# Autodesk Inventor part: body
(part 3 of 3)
sketch "Sketch150"
  geometry: L1 (-115, 140.221)-(-115, 134.332) reference; L2 (-115, 134.332)-(-122.377, 134.332) reference; L3 (-122.377, 134.332)-(-122.377, 140.221) reference; L4 (-122.377, 140.221)-(-115, 140.221) reference; L5 (-131, 141.166)-(-131, 148) reference; L6 (-131, 148)-(-123.589, 148) reference; L7 (-123.589, 148)-(-123.589, 141.166) reference; L8 (-123.589, 141.166)-(-131, 141.166) reference; L9 (-115, 141.166)-(-122.377, 141.166) reference; L10 (-122.377, 141.166)-(-122.377, 148) reference; L11 (-122.377, 148)-(-115, 148) reference; L12 (-115, 148)-(-115, 141.166) reference; L13 (-131, 140.221)-(-123.589, 140.221) reference; L14 (-123.589, 140.221)-(-123.589, 134.332) reference; L15 (-123.589, 134.332)-(-131, 134.332) reference; L16 (-131, 134.332)-(-131, 140.221) reference; L17 (-113.739, 149.568)-(-132.264, 149.568); L18 (-132.264, 149.568)-(-132.264, 132.978); L19 (-132.264, 132.978)-(-113.739, 132.978); L20 (-113.739, 132.978)-(-113.739, 149.568); 1 further point
  constraints: 8 end point, 2 parallel, 1 horizontal, 1 perpendicular
extrude "Extrusion150" cut sketch "Sketch150" distance "d349" = 1.25; taper "d350" = 0 deg
sketch "Sketch151"
  geometry: L1 (126.488, 149.508)-(126.488, 118) reference; L2 (126.488, 118)-(100, 118) reference; L3 (100, 118)-(100, 149.508) reference; L4 (100, 149.508)-(126.488, 149.508) reference; L5 (125.254, 134.332)-(101.544, 134.332); L6 (101.544, 134.332)-(101.544, 148.025); L7 (101.544, 148.025)-(125.254, 148.025); L8 (125.254, 148.025)-(125.254, 134.332); L9 (125.254, 132.001)-(101.544, 132.001); L10 (101.544, 132.001)-(101.544, 118.95); L11 (101.544, 118.95)-(125.254, 118.95); L12 (125.254, 118.95)-(125.254, 132.001); 1 further point
  constraints: 16 end point, 4 parallel, 2 horizontal, 2 perpendicular
extrude "Extrusion151" join sketch "Sketch151" distance "d351" = 1.25; taper "d352" = 0 deg
sketch "Sketch152"
  geometry: L1 (-125.254, 134.332)-(-125.254, 148.025) reference; L2 (-125.254, 148.025)-(-101.544, 148.025) reference; L3 (-101.544, 148.025)-(-101.544, 134.332) reference; L4 (-101.544, 134.332)-(-125.254, 134.332) reference; L5 (-126.488, 118)-(-126.488, 149.508) reference; L6 (-100, 149.508)-(-100, 118) reference; L7 (-126.488, 149.508)-(-100, 149.508) reference; L8 (-126.488, 132.993)-(-100, 132.993); 1 further point
  constraints: 2 end point, 2 point on line, 1 parallel
extrude "Extrusion152" join sketch "Sketch152" distance "d353" = 1.25; taper "d354" = 0 deg
sketch "Sketch153"
  geometry: L1 (101.544, 118.95)-(101.544, 132.001) reference; L2 (125.254, 132.001)-(125.254, 118.95) reference; L3 (125.254, 118.95)-(101.544, 118.95) reference; L4 (125.254, 148.025)-(125.254, 134.332) reference; L5 (101.544, 134.332)-(101.544, 148.025) reference; L6 (101.544, 148.025)-(125.254, 148.025) reference; L7 (125.254, 141.178)-(101.544, 141.178); L8 (101.544, 141.178)-(101.544, 140.119); L9 (101.544, 140.119)-(125.254, 140.119); L10 (125.254, 140.119)-(125.254, 141.178); L11 (125.254, 126.04)-(101.544, 126.04); L12 (101.544, 126.04)-(101.544, 124.925); L13 (101.544, 124.925)-(125.254, 124.925); L14 (125.254, 124.925)-(125.254, 126.04); L15 (108.73, 148.025)-(109.845, 148.025); L16 (109.845, 148.025)-(109.845, 118.95); L17 (109.845, 118.95)-(108.73, 118.95); L18 (108.73, 118.95)-(108.73, 148.025); L19 (117.478, 148.025)-(118.766, 148.025); L20 (118.766, 148.025)-(118.766, 118.95); L21 (118.766, 118.95)-(117.478, 118.95); L22 (117.478, 118.95)-(117.478, 148.025); 1 further point
  constraints: 32 end point, 8 parallel, 7 point on line, 4 horizontal, 4 perpendicular, 1 midpoint
extrude "Extrusion153" join sketch "Sketch153" distance "d355" = 0.75; taper "d356" = 0 deg
sketch "Sketch154"
  geometry: L1 (-117.478, 134.332)-(-118.766, 134.332) reference; L2 (-117.478, 134.332)-(-117.478, 140.119) reference; L3 (-117.478, 140.119)-(-109.845, 140.119) reference; L4 (-109.845, 140.119)-(-109.845, 134.332) reference; L5 (-108.73, 134.332)-(-109.845, 134.332) reference; L6 (-108.73, 134.332)-(-108.73, 140.119) reference; L7 (-108.73, 140.119)-(-101.544, 140.119) reference; L8 (-101.544, 141.178)-(-101.544, 140.119) reference; L9 (-101.544, 141.178)-(-108.73, 141.178) reference; L10 (-108.73, 141.178)-(-108.73, 148.025) reference; L11 (-109.845, 148.025)-(-108.73, 148.025) reference; L12 (-109.845, 148.025)-(-109.845, 141.178) reference; L13 (-109.845, 141.178)-(-117.478, 141.178) reference; L14 (-117.478, 141.178)-(-117.478, 148.025) reference; L15 (-118.766, 148.025)-(-117.478, 148.025) reference; L16 (-118.766, 148.025)-(-118.766, 141.178) reference; L17 (-118.766, 141.178)-(-125.254, 141.178) reference; L18 (-125.254, 140.119)-(-125.254, 141.178) reference; L19 (-125.254, 140.119)-(-118.766, 140.119) reference; L20 (-118.766, 140.119)-(-118.766, 134.332) reference; 1 further point
extrude "Extrusion154" join sketch "Sketch154" distance "d357" = 0.75; taper "d358" = 0 deg
sketch "Sketch155"
  geometry: L1 (117.478, 134.332)-(109.845, 134.332) reference; L2 (109.845, 134.332)-(109.845, 140.119) reference; L3 (109.845, 140.119)-(117.478, 140.119) reference; L4 (117.478, 140.119)-(117.478, 134.332) reference; L5 (108.73, 134.332)-(101.544, 134.332) reference; L6 (101.544, 134.332)-(101.544, 140.119) reference; L7 (101.544, 140.119)-(108.73, 140.119) reference; L8 (108.73, 140.119)-(108.73, 134.332) reference; L9 (118.766, 134.332)-(118.766, 140.119) reference; L10 (118.766, 140.119)-(125.254, 140.119) reference; L11 (125.254, 140.119)-(125.254, 134.332) reference; L12 (125.254, 134.332)-(118.766, 134.332) reference; L13 (101.544, 141.178)-(101.544, 148.025) reference; L14 (101.544, 148.025)-(108.73, 148.025) reference; L15 (108.73, 148.025)-(108.73, 141.178) reference; L16 (108.73, 141.178)-(101.544, 141.178) reference; L17 (109.845, 148.025)-(117.478, 148.025) reference; L18 (117.478, 148.025)-(117.478, 141.178) reference; L19 (117.478, 141.178)-(109.845, 141.178) reference; L20 (109.845, 141.178)-(109.845, 148.025) reference; L21 (125.254, 141.178)-(118.766, 141.178) reference; L22 (118.766, 141.178)-(118.766, 148.025) reference; L23 (118.766, 148.025)-(125.254, 148.025) reference; L24 (125.254, 148.025)-(125.254, 141.178) reference; L25 (99.825, 132.904)-(126.573, 132.904); L26 (126.573, 132.904)-(126.573, 149.564); L27 (126.573, 149.564)-(99.825, 149.564); L28 (99.825, 149.564)-(99.825, 132.904); 1 further point
  constraints: 8 end point, 2 parallel, 1 horizontal, 1 perpendicular
extrude "Extrusion155" cut sketch "Sketch155" distance "d359" = 0.75; taper "d360" = 0 deg
sketch "Sketch156"
  geometry: L1 (-132.114, -65.343)-(-128.305, -65.343); L2 (-128.305, -65.343)-(-128.305, -73.595); L3 (-128.305, -73.595)-(-132.114, -73.595); L4 (-132.114, -73.595)-(-132.114, -65.343); 1 further point
  constraints: 8 end point, 2 parallel, 1 horizontal, 1 perpendicular
extrude "Extrusion156" join sketch "Sketch156" distance "d361" = 6; taper "d363" = 0 deg; dims "d362" = 135.125, "d364" = 0
chamfer "Chamfer10" distance "d365" = 2; stored, may be unused: second distance "d366" = 2, angle "d367" = 45 deg
chamfer "Chamfer11" distance "d368" = 2.99; stored, may be unused: second distance "d369" = 2, angle "d370" = 45 deg
chamfer "Chamfer12" distance "d371" = 6.6; stored, may be unused: second distance "d372" = 2, angle "d373" = 45 deg
chamfer "Chamfer13" distance "d374" = 6.49; stored, may be unused: second distance "d375" = 2, angle "d376" = 45 deg
chamfer "Chamfer14" distance "d377" = 6.49; stored, may be unused: second distance "d378" = 2, angle "d379" = 45 deg
sketch "Sketch157"
  geometry: L1 (86, -22.522)-(104, -22.522) reference; L2 (104, -55)-(86, -55) reference; L3 (26, -55)-(8, -55) reference; L4 (8, -22.522)-(26, -22.522) reference; L5 (26, -22.522)-(26, -55) reference; L6 (17, -22.522)-(16, -22.522); L7 (16, -22.522)-(16, -55); L8 (16, -55)-(17, -55); L9 (17, -55)-(17, -22.522); L10 (17, -55)-(18, -55); L11 (18, -55)-(18, -22.522); L12 (18, -22.522)-(17, -22.522); L13 (17, -22.522)-(17, -55); L14 (95, -22.522)-(94, -22.522); L15 (94, -22.522)-(94, -55); L16 (94, -55)-(95, -55); L17 (95, -55)-(95, -22.522); L18 (95, -55)-(96, -55); L19 (96, -55)-(96, -22.522); L20 (96, -22.522)-(95, -22.522); L21 (95, -22.522)-(95, -55); L22 (104.519, -39.261)-(85.481, -39.261); L23 (85.481, -39.261)-(85.481, -38.261); L24 (85.481, -38.261)-(104.519, -38.261); L25 (104.519, -38.261)-(104.519, -39.261); L26 (104.519, -39.261)-(85.481, -38.261); L27 (85.481, -39.261)-(104.519, -38.261); L28 (8, -39.761)-(26, -39.761); L29 (26, -39.761)-(26, -38.761); L30 (26, -38.761)-(8, -38.761); L31 (8, -38.761)-(8, -39.761); L32 (8, -39.761)-(26, -38.761); L33 (26, -39.761)-(8, -38.761); 3 further points
  constraints: 56 end point, 12 parallel, 8 midpoint, 6 horizontal, 6 perpendicular, 5 point on line
  dimensions: "d380" = 1 distance of L8.end L7.end; "d381" = 1 distance of L12.end L11.end; "d382" = 1 distance of L16.end L15.end; "d383" = 1 distance of L20.end L19.end; "d384" = 1 distance of L22.end L23.end
extrude "Extrusion157" join sketch "Sketch157" distance "d385" = 2; taper "d386" = 0 deg
sketch "Sketch158"
  geometry: L1 (104.795, -31.141)-(85.205, -31.141); L2 (85.205, -31.141)-(85.205, -30.141); L3 (85.205, -30.141)-(104.795, -30.141); L4 (104.795, -30.141)-(104.795, -31.141); L5 (104.795, -31.141)-(85.205, -30.141); L6 (85.205, -31.141)-(104.795, -30.141); L7 (105.662, -47.88)-(84.338, -47.88); L8 (84.338, -47.88)-(84.338, -46.88); L9 (84.338, -46.88)-(105.662, -46.88); L10 (105.662, -46.88)-(105.662, -47.88); L11 (105.662, -47.88)-(84.338, -46.88); L12 (84.338, -47.88)-(105.662, -46.88); L13 (6.154, -30.141)-(27.846, -30.141); L14 (27.846, -30.141)-(27.846, -31.141); L15 (27.846, -31.141)-(6.154, -31.141); L16 (6.154, -31.141)-(6.154, -30.141); L17 (6.154, -30.141)-(27.846, -31.141); L18 (27.846, -30.141)-(6.154, -31.141); L19 (6.926, -46.88)-(27.074, -46.88); L20 (27.074, -46.88)-(27.074, -47.88); L21 (27.074, -47.88)-(6.926, -47.88); L22 (6.926, -47.88)-(6.926, -46.88); L23 (6.926, -46.88)-(27.074, -47.88); L24 (27.074, -46.88)-(6.926, -47.88); 5 further points
  constraints: 48 end point, 8 midpoint, 8 parallel, 4 horizontal, 4 perpendicular
  dimensions: "d387" = 1 distance of L1.end L2.end; "d388" = 1 distance of L7.end L8.end
extrude "Extrusion158" join sketch "Sketch158" distance "d389" = 2; taper "d390" = 0 deg
sketch "Sketch159"
  geometry: L1 (14, -178)-(126, -178) reference; L2 (31.976, -34.46)-(20.875, -34.46) reference; L3 (120.832, -178)-(115.933, -182.888); L4 (115.933, -182.888)-(24.079, -182.888); L5 (24.079, -182.888)-(19.202, -178); 1 further point
  constraints: 6 end point, 2 point on line, 1 parallel, 1 perpendicular
extrude "Extrusion159" join sketch "Sketch159" distance "d391" = 4.00022; taper "d392" = 0 deg
sketch "Sketch160"
  geometry: L1 (78, -15)-(34, -15); L2 (34, -15)-(34, -124); L3 (34, -124)-(78, -124); L4 (78, -124)-(78, -15); 1 further point
  constraints: 8 end point, 2 parallel, 1 horizontal, 1 perpendicular
extrude "Extrusion160" join sketch "Sketch160" distance "d393" = 4; taper "d394" = 0 deg
fillet "Fillet4" dims "d395" = 10
chamfer "Chamfer15" distance "d396" = 4; stored, may be unused: second distance "d397" = 2, angle "d398" = 45 deg
sketch "Sketch161"
  geometry: L1 (74, -47.663)-(74, -114) reference; L2 (56, -56)-(56, -32); L3 (53, -56)-(53, -32); L4 (59, -32)-(59, -56); L5 (56, -107)-(56, -83); L6 (53, -107)-(53, -83); L7 (59, -83)-(59, -107); C1 r 7 at (56, -107); C2 r 7 at (56, -56); A1 r 3 centre (56, -56) between (53, -56) and (59, -56); A2 r 3 centre (56, -32) between (59, -32) and (53, -32); A3 r 3 centre (56, -107) between (53, -107) and (59, -107); A4 r 3 centre (56, -83) between (59, -83) and (53, -83); 3 further points
  constraints: 16 end point, 8 point on circle, 8 tangent, 6 centre point, 4 parallel, 2 midpoint
extrude "Extrusion161" cut sketch "Sketch161" distance "d399" = 10.75; taper "d400" = 0 deg
sketch "Sketch162"
  geometry: L1 (53, -49.675)-(53, -32) reference; L2 (59, -32)-(59, -49.675) reference; L3 (53, -100.675)-(53, -83) reference; L4 (59, -83)-(59, -100.675) reference; L5 (38, -114)-(38, -47.663) reference; L6 (56, -107)-(56, -83); L7 (49, -107)-(49, -83); L8 (63, -83)-(63, -107); L9 (56, -56)-(56, -32); L10 (49, -56)-(49, -32); L11 (63, -32)-(63, -56); A1 r 3 centre (56, -32) between (59, -32) and (53, -32) reference; A2 r 7 centre (56, -56) between (53, -49.675) and (59, -49.675) reference; A3 r 3 centre (56, -83) between (59, -83) and (53, -83) reference; A4 r 7 centre (56, -107) between (53, -100.675) and (59, -100.675) reference; A5 r 7 centre (56, -107) between (49, -107) and (63, -107); A6 r 7 centre (56, -83) between (63, -83) and (49, -83); A7 r 7 centre (56, -56) between (49, -56) and (63, -56); A8 r 7 centre (56, -32) between (63, -32) and (49, -32); 3 further points
  constraints: 16 end point, 8 point on circle, 8 tangent, 4 centre point, 4 parallel, 2 midpoint
extrude "Extrusion162" cut sketch "Sketch162" distance "d401" = 4; taper "d402" = 0 deg
chamfer "Chamfer16" distance "d403" = 3; stored, may be unused: second distance "d404" = 2, angle "d405" = 45 deg
fillet "Fillet5" dims "d406" = 6
sketch "Sketch163"
  geometry: L1 (0, 0)-(0, 86) reference; L2 (112, 0)-(0, 0); L3 (0, 0)-(0, 5); L4 (0, 5)-(112, 5); L5 (112, 5)-(112, 0); 1 further point
  constraints: 8 end point, 2 parallel, 1 horizontal, 1 perpendicular, 1 point on line
extrude "Extrusion163" join sketch "Sketch163" distance "d407" = 6; taper "d408" = 0 deg
chamfer "Chamfer17" distance "d409" = 6; stored, may be unused: second distance "d410" = 2, angle "d411" = 45 deg
sketch "Sketch164"
  geometry: L1 (112, -66.522)-(107, -66.522); L2 (107, -66.522)-(107, -62); L3 (107, -62)-(112, -62); L4 (112, -62)-(112, -66.522); L5 (0, -66.522)-(5, -66.522); L6 (5, -66.522)-(5, -62); L7 (5, -62)-(0, -62); L8 (0, -62)-(0, -66.522); 1 further point
  constraints: 16 end point, 4 parallel, 2 horizontal, 2 perpendicular
extrude "Extrusion164" join sketch "Sketch164" distance "d412" = 87; taper "d413" = 0 deg
chamfer "Chamfer18" distance "d414" = 5; stored, may be unused: second distance "d415" = 2, angle "d416" = 45 deg
sketch "Sketch165"
  geometry: L1 (14, -200)-(14, -178) reference; L2 (115.933, -182.888)-(120.832, -178) reference; L3 (126, -178)-(126, -200) reference; L4 (31.976, -34.46)-(20.875, -34.46) reference; L5 (14, -196.844)-(18.833, -196.844); L6 (18.833, -196.844)-(18.833, -186.125); L7 (18.833, -186.125)-(14, -181.281); L8 (126, -196.844)-(121.146, -196.844); L9 (121.146, -196.844)-(121.146, -186.125); L10 (121.146, -186.125)-(126, -181.282); 1 further point
  constraints: 12 end point, 5 perpendicular, 4 point on line, 1 parallel
extrude "Extrusion165" join sketch "Sketch165" distance "d417" = 90.22222; taper "d418" = 0 deg
chamfer "Chamfer19" distance "d419" = 4.75; stored, may be unused: second distance "d420" = 2, angle "d421" = 45 deg
chamfer "Chamfer20" distance "d422" = 1; stored, may be unused: second distance "d423" = 2, angle "d424" = 45 deg
chamfer "Chamfer21" distance "d425" = 0.5; stored, may be unused: second distance "d426" = 2, angle "d427" = 45 deg
chamfer "Chamfer22" distance "d428" = 0.5; stored, may be unused: second distance "d429" = 2, angle "d430" = 45 deg
chamfer "Chamfer23" distance "d431" = 0.5; stored, may be unused: second distance "d432" = 2, angle "d433" = 45 deg
chamfer "Chamfer24" distance "d434" = 0.5; stored, may be unused: second distance "d435" = 2, angle "d436" = 45 deg
chamfer "Chamfer25" distance "d437" = 0.5; stored, may be unused: second distance "d438" = 2, angle "d439" = 45 deg
chamfer "Chamfer26" distance "d440" = 0.5; stored, may be unused: second distance "d441" = 2, angle "d442" = 45 deg
chamfer "Chamfer27" distance "d443" = 2; stored, may be unused: second distance "d444" = 0.5, angle "d445" = 45 deg
chamfer "Chamfer28" distance "d446" = 2; stored, may be unused: second distance "d447" = 0.5, angle "d448" = 45 deg
chamfer "Chamfer29" distance "d449" = 2; stored, may be unused: second distance "d450" = 0.5, angle "d451" = 45 deg
chamfer "Chamfer30" distance "d452" = 2; stored, may be unused: second distance "d453" = 0.5, angle "d454" = 45 deg
chamfer "Chamfer31" distance "d455" = 1.5; stored, may be unused: second distance "d456" = 0.5, angle "d457" = 45 deg
chamfer "Chamfer32" distance "d458" = 2; stored, may be unused: second distance "d459" = 0.5, angle "d460" = 45 deg
chamfer "Chamfer33" distance "d461" = 2; stored, may be unused: second distance "d462" = 0.5, angle "d463" = 45 deg
chamfer "Chamfer34" distance "d464" = 2; stored, may be unused: second distance "d465" = 0.5, angle "d466" = 45 deg
chamfer "Chamfer35" distance "d467" = 2; stored, may be unused: second distance "d468" = 0.5, angle "d469" = 45 deg
chamfer "Chamfer36" distance "d470" = 2; stored, may be unused: second distance "d471" = 0.5, angle "d472" = 45 deg
chamfer "Chamfer37" distance "d473" = 2; stored, may be unused: second distance "d474" = 0.5, angle "d475" = 45 deg
chamfer "Chamfer38" distance "d476" = 2; stored, may be unused: second distance "d477" = 0.5, angle "d478" = 45 deg
chamfer "Chamfer39" distance "d479" = 2; stored, may be unused: second distance "d480" = 0.5, angle "d481" = 45 deg
chamfer "Chamfer40" distance "d482" = 2; stored, may be unused: second distance "d483" = 0.5, angle "d484" = 45 deg
chamfer "Chamfer41" distance "d485" = 2; stored, may be unused: second distance "d486" = 0.5, angle "d487" = 45 deg
chamfer "Chamfer42" distance "d488" = 2; stored, may be unused: second distance "d489" = 0.5, angle "d490" = 45 deg
chamfer "Chamfer43" distance "d491" = 2; stored, may be unused: second distance "d492" = 0.5, angle "d493" = 45 deg
chamfer "Chamfer44" distance "d494" = 1.75; stored, may be unused: second distance "d495" = 0.5, angle "d496" = 45 deg
chamfer "Chamfer45" distance "d497" = 2; stored, may be unused: second distance "d498" = 0.5, angle "d499" = 45 deg
chamfer "Chamfer46" distance "d500" = 2; stored, may be unused: second distance "d501" = 0.5, angle "d502" = 45 deg
chamfer "Chamfer47" distance "d503" = 2; stored, may be unused: second distance "d504" = 0.5, angle "d505" = 45 deg
chamfer "Chamfer48" distance "d506" = 2; stored, may be unused: second distance "d507" = 0.5, angle "d508" = 45 deg
chamfer "Chamfer49" distance "d509" = 2; stored, may be unused: second distance "d510" = 0.5, angle "d511" = 45 deg
chamfer "Chamfer50" distance "d512" = 2; stored, may be unused: second distance "d513" = 0.5, angle "d514" = 45 deg
chamfer "Chamfer51" distance "d515" = 2; stored, may be unused: second distance "d516" = 0.5, angle "d517" = 45 deg
chamfer "Chamfer52" distance "d518" = 2; stored, may be unused: second distance "d519" = 0.5, angle "d520" = 45 deg
chamfer "Chamfer53" distance "d521" = 2; stored, may be unused: second distance "d522" = 0.5, angle "d523" = 45 deg
chamfer "Chamfer54" distance "d524" = 2; stored, may be unused: second distance "d525" = 0.5, angle "d526" = 45 deg
chamfer "Chamfer55" distance "d527" = 2; stored, may be unused: second distance "d528" = 0.5, angle "d529" = 45 deg
chamfer "Chamfer56" distance "d530" = 2; stored, may be unused: second distance "d531" = 0.5, angle "d532" = 45 deg
chamfer "Chamfer57" distance "d533" = 2; stored, may be unused: second distance "d534" = 0.5, angle "d535" = 45 deg
chamfer "Chamfer58" distance "d536" = 2; stored, may be unused: second distance "d537" = 0.5, angle "d538" = 45 deg
chamfer "Chamfer59" distance "d539" = 2; stored, may be unused: second distance "d540" = 0.5, angle "d541" = 45 deg
chamfer "Chamfer60" distance "d542" = 2; stored, may be unused: second distance "d543" = 0.5, angle "d544" = 45 deg
chamfer "Chamfer61" distance "d545" = 2; stored, may be unused: second distance "d546" = 0.5, angle "d547" = 45 deg
chamfer "Chamfer62" distance "d548" = 2; stored, may be unused: second distance "d549" = 0.5, angle "d550" = 45 deg
chamfer "Chamfer63" distance "d551" = 2; stored, may be unused: second distance "d552" = 0.5, angle "d553" = 45 deg
chamfer "Chamfer64" distance "d554" = 2; stored, may be unused: second distance "d555" = 0.5, angle "d556" = 45 deg
chamfer "Chamfer65" distance "d557" = 2; stored, may be unused: second distance "d558" = 0.5, angle "d559" = 45 deg
chamfer "Chamfer66" distance "d560" = 2; stored, may be unused: second distance "d561" = 0.5, angle "d562" = 45 deg
chamfer "Chamfer67" distance "d563" = 2; stored, may be unused: second distance "d564" = 0.5, angle "d565" = 45 deg
chamfer "Chamfer68" distance "d566" = 2; stored, may be unused: second distance "d567" = 0.5, angle "d568" = 45 deg
chamfer "Chamfer69" distance "d569" = 2; stored, may be unused: second distance "d570" = 0.5, angle "d571" = 45 deg
chamfer "Chamfer70" distance "d572" = 2; stored, may be unused: second distance "d573" = 0.5, angle "d574" = 45 deg
chamfer "Chamfer71" distance "d575" = 2; stored, may be unused: second distance "d576" = 0.5, angle "d577" = 45 deg
chamfer "Chamfer72" distance "d578" = 2; stored, may be unused: second distance "d579" = 0.5, angle "d580" = 45 deg
chamfer "Chamfer73" distance "d581" = 2; stored, may be unused: second distance "d582" = 0.5, angle "d583" = 45 deg
chamfer "Chamfer74" distance "d584" = 2; stored, may be unused: second distance "d585" = 0.5, angle "d586" = 45 deg
chamfer "Chamfer75" distance "d587" = 2; stored, may be unused: second distance "d588" = 0.5, angle "d589" = 45 deg
chamfer "Chamfer76" distance "d590" = 2; stored, may be unused: second distance "d591" = 0.5, angle "d592" = 45 deg
chamfer "Chamfer77" distance "d593" = 2; stored, may be unused: second distance "d594" = 0.5, angle "d595" = 45 deg
chamfer "Chamfer78" distance "d596" = 2; stored, may be unused: second distance "d597" = 0.5, angle "d598" = 45 deg
chamfer "Chamfer79" distance "d599" = 2; stored, may be unused: second distance "d600" = 0.5, angle "d601" = 45 deg
chamfer "Chamfer80" distance "d602" = 1.25; stored, may be unused: second distance "d603" = 0.5, angle "d604" = 45 deg
chamfer "Chamfer81" distance "d605" = 1.25; stored, may be unused: second distance "d606" = 0.5, angle "d607" = 45 deg
chamfer "Chamfer82" distance "d608" = 1.25; stored, may be unused: second distance "d609" = 0.5, angle "d610" = 45 deg
chamfer "Chamfer83" distance "d611" = 2; stored, may be unused: second distance "d612" = 0.5, angle "d613" = 45 deg
chamfer "Chamfer84" distance "d614" = 2; stored, may be unused: second distance "d615" = 0.5, angle "d616" = 45 deg
chamfer "Chamfer85" distance "d617" = 2; stored, may be unused: second distance "d618" = 0.5, angle "d619" = 45 deg
chamfer "Chamfer86" distance "d620" = 2; stored, may be unused: second distance "d621" = 0.5, angle "d622" = 45 deg
chamfer "Chamfer87" distance "d623" = 2; stored, may be unused: second distance "d624" = 0.5, angle "d625" = 45 deg
chamfer "Chamfer88" distance "d626" = 2; stored, may be unused: second distance "d627" = 0.5, angle "d628" = 45 deg
chamfer "Chamfer89" distance "d629" = 2; stored, may be unused: second distance "d630" = 0.5, angle "d631" = 45 deg
chamfer "Chamfer90" distance "d632" = 2; stored, may be unused: second distance "d633" = 0.5, angle "d634" = 45 deg
chamfer "Chamfer91" distance "d635" = 2; stored, may be unused: second distance "d636" = 0.5, angle "d637" = 45 deg
chamfer "Chamfer92" distance "d638" = 2; stored, may be unused: second distance "d639" = 0.5, angle "d640" = 45 deg
chamfer "Chamfer93" distance "d641" = 2; stored, may be unused: second distance "d642" = 0.5, angle "d643" = 45 deg
chamfer "Chamfer94" distance "d644" = 2; stored, may be unused: second distance "d645" = 0.5, angle "d646" = 45 deg
chamfer "Chamfer95" distance "d647" = 0.5; stored, may be unused: second distance "d648" = 0.5, angle "d649" = 45 deg
sketch "Sketch166"
  geometry: L1 (-9.13, -36.87)-(0.44, -36.87); L2 (0.44, -36.87)-(0.44, -53.44); L3 (0.44, -53.44)-(-9.13, -53.44); L4 (-9.13, -53.44)-(-9.13, -36.87); 1 further point
  constraints: 8 end point, 2 parallel, 1 horizontal, 1 perpendicular
extrude "Extrusion166" cut sketch "Sketch166" distance "d650" = 18.77778; taper "d651" = 0 deg
chamfer "Chamfer96" distance "d652" = 3.5; stored, may be unused: second distance "d653" = 0.5, angle "d654" = 45 deg
chamfer "Chamfer97" distance "d655" = 2; stored, may be unused: second distance "d656" = 0.5, angle "d657" = 45 deg
sketch "Sketch167"
  geometry: L1 (4, -55)-(4, -35) reference; L2 (2, -33)-(-11, -33) reference; L3 (-13, -35)-(-13, -55) reference; L4 (-4.5, -33)-(-6, -33); L5 (-6, -33)-(-6, -35); L6 (-6, -35)-(-4.5, -35); L7 (-4.5, -35)-(-4.5, -33); L8 (-4.5, -35)-(-3, -35); L9 (-3, -35)-(-3, -33); L10 (-3, -33)-(-4.5, -33); L11 (-4.5, -33)-(-4.5, -35); L12 (4, -45)-(2.5, -45); L13 (2.5, -45)-(2.5, -43); L14 (2.5, -43)-(4, -43); L15 (4, -43)-(4, -45); L16 (4, -45)-(2.5, -45); L17 (2.5, -45)-(2.5, -47); L18 (2.5, -47)-(4, -47); L19 (4, -47)-(4, -45); L20 (-13, -43)-(-11.5, -43); L21 (-11.5, -43)-(-11.5, -47); L22 (-11.5, -47)-(-13, -47); L23 (-13, -47)-(-13, -43); 1 further point
  constraints: 40 end point, 10 parallel, 5 horizontal, 5 perpendicular, 2 midpoint, 2 point on line
  dimensions: "d658" = 1.5 distance of L13.end L14.end; "d659" = 1.5 distance of L21.end L22.end
extrude "Extrusion167" join sketch "Sketch167" distance "d660" = 13.02778; taper "d661" = 0 deg
chamfer "Chamfer98" distance "d662" = 1.5; stored, may be unused: second distance "d663" = 0.5, angle "d664" = 45 deg
chamfer "Chamfer99" distance "d665" = 1.5; stored, may be unused: second distance "d666" = 0.5, angle "d667" = 45 deg
sketch "Sketch168"
  geometry: L1 (-1.712, 154.276)-(2.594, 154.276); L2 (2.594, 154.276)-(2.594, 150.276); L3 (2.594, 150.276)-(-4.582, 150.276); L4 (2.594, 149)-(2.594, 145); L5 (2.594, 145)-(-6.406, 145); L6 (-6.406, 145)-(-6.406, 147.734); L7 (-5.497, 149)-(2.594, 149); L8 (-7.671, 145.97)-(-7.671, 145); L9 (-7.671, 145)-(-8.367, 145); L10 (6, 144)-(6, 140); L11 (6, 140)-(-3, 140); L12 (-3, 140)-(-3, 144); L13 (-3, 144)-(6, 144); L14 (-4, 144)-(-4, 140); L15 (-4, 140)-(-11.954, 140); L16 (-9.084, 144)-(-4, 144); L17 (1, 139)-(1, 135); L18 (1, 135)-(-8, 135); L19 (-8, 135)-(-8, 139); L20 (-8, 139)-(1, 139); L21 (-9, 139)-(-9, 135); L22 (-9, 135)-(-15.541, 135); L23 (-12.671, 139)-(-9, 139); L24 (6, 134)-(6, 130); L25 (6, 130)-(-3, 130); L26 (-3, 130)-(-3, 134); L27 (-3, 134)-(6, 134); L28 (-4, 134)-(-4, 130); L29 (-4, 130)-(-13, 130); L30 (-13, 130)-(-13, 134); L31 (-13, 134)-(-4, 134); L32 (-14, 134)-(-14, 130); L33 (-14, 130)-(-19.128, 130); L34 (-16.258, 134)-(-14, 134); L35 (-9, 129)-(-9, 125); L36 (-9, 125)-(-18, 125); L37 (-18, 125)-(-18, 129); L38 (-18, 129)-(-9, 129); L39 (1, 129)-(1, 125); L40 (1, 125)-(-8, 125); L41 (-8, 125)-(-8, 129); L42 (-8, 129)-(1, 129); L43 (-19, 129)-(-19, 125); L44 (-19, 125)-(-22, 125); L45 (-19.845, 129)-(-19, 129); L46 (-3, 124)-(6, 124); L47 (6, 120)-(-3, 120); L48 (6, 124)-(6, 120); L49 (-4, 124)-(-4, 120); L50 (-8, 119)-(1, 119); L51 (1, 119)-(1, 115); L52 (1, 115)-(-8, 115); L53 (-8, 115)-(-8, 119); L54 (-3, 120)-(-3, 124); L55 (-13, 124)-(-4, 124); L56 (-4, 120)-(-13, 120); L57 (-13, 120)-(-13, 124); L58 (-18, 119)-(-9, 119); L59 (-9, 115)-(-18, 115); L60 (-9, 119)-(-9, 115); L61 (-18, 115)-(-18, 119); L62 (-19, 119)-(-19, 115); L63 (-14, 120)-(-23, 120); L64 (-23, 120)-(-23, 124)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; 1 further point
  constraints: 716 end point, 172 parallel, 88 horizontal, 88 perpendicular, 2 collinear, 2 point on line
extrude "Extrusion168" cut sketch "Sketch168" distance "d668" = 0.5; taper "d669" = 0 deg
sketch "Sketch169"
  geometry: L1 (0.5, 157)-(0.5, 144) reference; L2 (0.242, 157)-(0.5, 157) reference; L3 (-22, 124)-(-22, 125.957) reference; L4 (0.5, 14)-(-3, 14) reference; L5 (-9.072, 144)-(-4, 144); L6 (-4, 144)-(-4, 140); L7 (-4, 140)-(-11.938, 140); L8 (-9.072, 139)-(-9.072, 135); L9 (-9.072, 135)-(-15.521, 135); L10 (-9.072, 139)-(-12.655, 139); L11 (-14, 134)-(-14, 130); L12 (-14, 130)-(-19.103, 130); L13 (-14, 134)-(-16.237, 134); L14 (-19.82, 129)-(-19.103, 129); L15 (-19.103, 129)-(-19.103, 124.978); L16 (-19.103, 124.978)-(-22, 124.978); L17 (0.5, 145)-(-8.356, 145); L18 (0.5, 149.41)-(-5.196, 149.41); L19 (0.5, 150.5)-(-4.415, 150.5); 1 further point
  constraints: 30 end point, 8 parallel, 6 perpendicular, 2 midpoint, 2 point on line, 11 other
extrude "Extrusion169" join sketch "Sketch169" distance "d670" = 0.5; taper "d671" = 0 deg
sketch "Sketch170"
  geometry: L1 (-1.322, 151.905)-(-1.322, 144.25) reference; L2 (0, 151.905)-(0, 176.929) reference; L3 (-5.936, 162.782)-(-5.936, 173.075) reference; L4 (-6.364, 162)-(-6.364, 155.5) reference; L5 (-7.071, 9)-(0, 9); L6 (0, 9)-(0, 10); L7 (0, 10)-(-7.071, 10); L8 (-7.071, 10)-(-7.071, 9); L9 (-7.071, 14)-(0, 14); L10 (0, 14)-(0, 15); L11 (0, 15)-(-7.071, 15); L12 (-7.071, 15)-(-7.071, 14); L13 (-7.071, 19)-(0, 19); L14 (0, 19)-(0, 20); L15 (0, 20)-(-7.071, 20); L16 (-7.071, 20)-(-7.071, 19); L17 (-7.071, 24)-(0, 24); L18 (0, 24)-(0, 25); L19 (0, 25)-(-7.071, 25); L20 (-7.071, 25)-(-7.071, 24); L21 (-7.071, 29)-(0, 29); L22 (0, 29)-(0, 30); L23 (0, 30)-(-7.071, 30); L24 (-7.071, 30)-(-7.071, 29); L25 (-7.071, 34)-(0, 34); L26 (0, 34)-(0, 35); L27 (0, 35)-(-7.071, 35); L28 (-7.071, 35)-(-7.071, 34); L29 (-7.071, 39)-(0, 39); L30 (0, 39)-(0, 40); L31 (0, 40)-(-7.071, 40); L32 (-7.071, 40)-(-7.071, 39); L33 (-7.071, 44)-(0, 44); L34 (0, 44)-(0, 45); L35 (0, 45)-(-7.071, 45); L36 (-7.071, 45)-(-7.071, 44); L37 (-7.071, 49)-(0, 49); L38 (0, 49)-(0, 50); L39 (0, 50)-(-7.071, 50); L40 (-7.071, 50)-(-7.071, 49); L41 (-7.071, 54)-(0, 54); L42 (0, 54)-(0, 55); L43 (0, 55)-(-7.071, 55); L44 (-7.071, 55)-(-7.071, 54); L45 (-7.071, 59)-(0, 59); L46 (0, 59)-(0, 60); L47 (0, 60)-(-7.071, 60); L48 (-7.071, 60)-(-7.071, 59); L49 (-7.071, 64)-(0, 64); L50 (0, 64)-(0, 65); L51 (0, 65)-(-7.071, 65); L52 (-7.071, 65)-(-7.071, 64); L53 (-7.071, 69)-(0, 69); L54 (0, 69)-(0, 70); L55 (0, 70)-(-7.071, 70); L56 (-7.071, 70)-(-7.071, 69); L57 (-7.071, 74)-(0, 74); L58 (0, 74)-(0, 75); L59 (0, 75)-(-7.071, 75); L60 (-7.071, 75)-(-7.071, 74); L61 (-7.071, 79)-(0, 79); L62 (0, 79)-(0, 80); L63 (0, 80)-(-7.071, 80); L64 (-7.071, 80)-(-7.071, 79)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; 3 further points
  constraints: 264 end point, 66 parallel, 33 horizontal, 33 perpendicular, 9 point on line, 28 other
extrude "Extrusion170" cut sketch "Sketch170" distance "d672" = 0.5; taper "d673" = 0 deg
sketch "Sketch171"
  geometry: L1 (4.693, -136.789)-(4.693, -136.289) reference; L2 (4.693, -132.289)-(4.693, -131.289) reference; L3 (4.693, -127.289)-(4.693, -126.289) reference; L4 (4.693, -122.289)-(4.693, -121.289) reference; L5 (4.693, -117.289)-(4.693, -116.289) reference; L6 (4.693, -112.289)-(4.693, -111.289) reference; L7 (4.693, -107.289)-(4.693, -106.289) reference; L8 (4.693, -102.289)-(4.693, -101.289) reference; L9 (4.693, -97.289)-(4.693, -96.289) reference; L10 (4.693, -92.289)-(4.693, -91.289) reference; L11 (4.693, -87.289)-(4.693, -86.289) reference; L12 (4.693, -82.289)-(4.693, -81.289) reference; L13 (4.693, -77.289)-(4.693, -76.289) reference; L14 (4.693, -72.289)-(4.693, -71.289) reference; L15 (4.693, -67.289)-(4.693, -66.289) reference; L16 (4.693, -62.289)-(4.693, -61.289) reference; L17 (4.693, -57.289)-(4.693, -56.289) reference; L18 (4.693, -52.289)-(4.693, -51.289) reference; L19 (4.693, -47.289)-(4.693, -46.289) reference; L20 (4.693, -42.289)-(4.693, -41.289) reference; L21 (4.693, -37.289)-(4.693, -36.289) reference; L22 (4.693, -32.289)-(4.693, -31.289) reference; L23 (4.693, -27.289)-(4.693, -26.289) reference; L24 (4.693, -22.289)-(4.693, -21.289) reference; L25 (4.693, -17.289)-(4.693, -16.289) reference; L26 (4.693, -12.289)-(4.693, -11.311) reference; L27 (0.066, -12.024)-(-0.044, -11.149) reference; L28 (-0.372, -12.52)-(0.066, -12.024) reference; L29 (0.066, -20.024)-(-0.872, -12.52) reference; L30 (0.066, -28.024)-(-0.872, -20.52) reference; L31 (0.066, -36.024)-(-0.872, -28.52) reference; L32 (-0.372, -36.52)-(0.066, -36.024) reference; L33 (-0.872, -36.52)-(-0.372, -36.52) reference; L34 (0.066, -44.024)-(-0.872, -36.52) reference; L35 (0.066, -52.024)-(-0.872, -44.52) reference; L36 (-0.372, -52.52)-(0.066, -52.024) reference; L37 (0.066, -60.024)-(-0.872, -52.52) reference; L38 (0.066, -68.024)-(-0.872, -60.52) reference; L39 (0.066, -76.024)-(-0.872, -68.52) reference; L40 (-0.372, -76.52)-(0.066, -76.024) reference; L41 (-0.872, -76.52)-(-0.372, -76.52) reference; L42 (0.066, -84.024)-(-0.872, -76.52) reference; L43 (0.066, -92.024)-(-0.872, -84.52) reference; L44 (-0.372, -92.52)-(0.066, -92.024) reference; L45 (0.066, -100.024)-(-0.872, -92.52) reference; L46 (0.066, -108.024)-(-0.872, -100.52) reference; L47 (0.066, -116.024)-(-0.872, -108.52) reference; L48 (-0.372, -116.52)-(0.066, -116.024) reference; L49 (-0.872, -116.52)-(-0.372, -116.52) reference; L50 (0.066, -124.024)-(-0.872, -116.52) reference; L51 (0.066, -132.024)-(-0.872, -124.52) reference; L52 (-0.368, -132.583)-(0.066, -132.024) reference; L53 (0.128, -140.645)-(-0.872, -132.645) reference; L54 (-0.436, -141.289)-(0.128, -140.645) reference; L55 (0.193, -141.289)-(-0.436, -141.289) reference; L56 (4.693, -136.789)-(0.193, -141.289) reference; L57 (4.693, -11.311)-(-0.044, -11.149); L58 (4.693, -12.289)-(-0.153, -12.272); L59 (4.693, -16.289)-(-0.403, -16.272); L60 (4.693, -17.289)-(-0.278, -17.273); L61 (4.693, -21.289)-(-0.778, -21.271); L62 (4.693, -22.289)-(-0.653, -22.272); L63 (4.693, -26.289)-(-0.153, -26.273); L64 (4.693, -27.289)-(-0.028, -27.274)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; 1 further point
  constraints: 102 end point, 39 parallel, 39 point on line, 11 midpoint
extrude "Extrusion171" cut sketch "Sketch171" distance "d674" = 0.5; taper "d675" = 0 deg
sketch "Sketch172"
  geometry: L1 (78, -66.522)-(107, -66.522) reference; L2 (107, -66.522)-(107, -62) reference; L3 (34, -66.522)-(5, -66.522); L4 (5, -66.522)-(5, -62); L5 (5, -62)-(34, -62); L6 (34, -62)-(34, -66.522); L7 (78, -66.522)-(107, -66.522); L8 (107, -66.522)-(107, -62); L9 (107, -62)-(78, -62); L10 (78, -62)-(78, -66.522); 1 further point
  constraints: 16 end point, 4 parallel, 2 horizontal, 2 perpendicular
extrude "Extrusion172" join sketch "Sketch172" distance "d676" = 29; taper "d677" = 0 deg
chamfer "Chamfer100" distance "d678" = 29; stored, may be unused: second distance "d679" = 0.5, angle "d680" = 45 deg
sketch "Sketch173"
  geometry: L1 (112, 4.183)-(112, -57) reference; L2 (0, -57)-(0, 4.183) reference; L3 (34, -22.522)-(0, -22.522); L4 (0, -22.522)-(0, -19); L5 (0, -19)-(34, -19); L6 (34, -19)-(34, -22.522); L7 (78, -22.522)-(112, -22.522); L8 (112, -22.522)-(112, -19); L9 (112, -19)-(78, -19); L10 (78, -19)-(78, -22.522); 1 further point
  constraints: 16 end point, 4 parallel, 2 horizontal, 2 perpendicular, 2 point on line
extrude "Extrusion173" join sketch "Sketch173" distance "d681" = 34; taper "d682" = 0 deg
chamfer "Chamfer101" distance "d683" = 34; stored, may be unused: second distance "d684" = 0.5, angle "d685" = 45 deg
chamfer "Chamfer102" distance "d686" = 8; stored, may be unused: second distance "d687" = 0.5, angle "d688" = 45 deg
chamfer "Chamfer103" distance "d689" = 7; stored, may be unused: second distance "d690" = 0.5, angle "d691" = 45 deg
sketch "Sketch174"
  geometry: L1 (18, -20)-(16, -20); L2 (16, -20)-(16, -57.407); L3 (16, -57.407)-(18, -57.407); L4 (18, -57.407)-(18, -20); L5 (26, -20)-(28, -20); L6 (28, -20)-(28, -57.407); L7 (28, -57.407)-(26, -57.407); L8 (26, -57.407)-(26, -20); L9 (34, -57.407)-(32, -57.407); L10 (32, -57.407)-(32, -20); L11 (32, -20)-(34, -20); L12 (34, -20)-(34, -57.407); 1 further point
  constraints: 24 end point, 6 parallel, 3 horizontal, 3 perpendicular
extrude "Extrusion174" join sketch "Sketch174" distance "d692" = 1; taper "d693" = 0 deg
sketch "Sketch175"
  geometry: L1 (96, -20)-(94, -20); L2 (94, -20)-(94, -58); L3 (94, -58)-(96, -58); L4 (96, -58)-(96, -20); L5 (86, -20)-(84, -20); L6 (84, -20)-(84, -58); L7 (84, -58)-(86, -58); L8 (86, -58)-(86, -20); L9 (78, -20)-(80, -20); L10 (80, -20)-(80, -58); L11 (80, -58)-(78, -58); L12 (78, -58)-(78, -20); 1 further point
  constraints: 24 end point, 6 parallel, 3 horizontal, 3 perpendicular
extrude "Extrusion175" join sketch "Sketch175" distance "d694" = 1; taper "d695" = 0 deg
chamfer "Chamfer104" distance "d696" = 1; stored, may be unused: second distance "d697" = 0.5, angle "d698" = 45 deg
chamfer "Chamfer105" distance "d699" = 0.6; stored, may be unused: second distance "d700" = 0.5, angle "d701" = 45 deg
sketch "Sketch176"
  geometry: L1 (78, -19)-(112, -19) reference; L2 (29, -22.522)-(83, -22.522); L3 (83, -22.522)-(83, -19); L4 (83, -19)-(29, -19); L5 (29, -19)-(29, -22.522); 1 further point
  constraints: 8 end point, 2 parallel, 1 horizontal, 1 perpendicular, 1 point on line
extrude "Extrusion176" join sketch "Sketch176" distance "d702" = 2; taper "d703" = 0 deg
chamfer "Chamfer106" distance "d704" = 2; stored, may be unused: second distance "d705" = 0.5, angle "d706" = 45 deg
sketch "Sketch177"
  geometry: L1 (0, -19)-(112, -19) reference; L2 (0, 4.183)-(112, 4.183) reference; L3 (34, -19)-(32, -19); L4 (32, -19)-(32, 4.183); L5 (32, 4.183)-(34, 4.183); L6 (34, 4.183)-(34, -19); L7 (78, -19)-(80, -19); L8 (80, -19)-(80, 4.183); L9 (80, 4.183)-(78, 4.183); L10 (78, 4.183)-(78, -19); 1 further point
  constraints: 16 end point, 4 parallel, 3 point on line, 2 horizontal, 2 perpendicular
extrude "Extrusion177" join sketch "Sketch177" distance "d707" = 18; taper "d708" = 0 deg
sketch "Sketch178"
  geometry: L1 (0, 23.183)-(-18, 23.183) reference; L2 (0, 0)-(-2, 0) reference; L3 (-18, 23.183)-(-18, 42); L4 (-12.96, 42)-(0, 24); L5 (0, 24)-(0, 23.183); L6 (0, 24)-(0, 23.183); L7 (-2, 0)-(-18, 0) reference; L8 (-12.96, 42)-(-18, 42); 1 further point
  constraints: 10 end point, 2 parallel, 1 collinear, 1 perpendicular
extrude "Extrusion178" join sketch "Sketch178" distance "d709" = 2; taper "d710" = 0 deg
sketch "Sketch179"
  geometry: L1 (0, 23.183)-(18, 23.183) reference; L2 (18, 23.183)-(18, 41.728); L3 (18, 41.728)-(12, 41.728); L4 (12, 41.728)-(0, 24); L5 (0, 24)-(0, 23.183); 1 further point
  constraints: 8 end point, 2 perpendicular, 1 parallel
extrude "Extrusion179" join sketch "Sketch179" distance "d711" = 2; taper "d712" = 0 deg
sketch "Sketch180"
  geometry: L1 (32, -19)-(32, 19.478) reference; L2 (32, -19)-(34, -19) reference; L3 (34, -19)-(34, 19.478) reference; L4 (32, 19.478)-(34, 19.478) reference; 1 further point
extrude "Extrusion180" join sketch "Sketch180" distance "d713" = 6; taper "d714" = 0 deg
sketch "Sketch181"
  geometry: L1 (78, -19)-(80, -19) reference; L2 (80, -19)-(80, 19.478) reference; L3 (78, 19.478)-(80, 19.478) reference; L4 (78, -19)-(78, 19.478) reference; 1 further point
extrude "Extrusion181" join sketch "Sketch181" distance "d715" = 4.25; taper "d716" = 0 deg
chamfer "Chamfer107" distance "d717" = 38.25; stored, may be unused: second distance "d718" = 22, angle "d719" = 45 deg
chamfer "Chamfer108" distance "d720" = 38.25; stored, may be unused: second distance "d721" = 20.25, angle "d722" = 45 deg
chamfer "Chamfer109" distance "d723" = 8; stored, may be unused: second distance "d724" = 20.25, angle "d725" = 45 deg
sketch "Sketch182"
  geometry: L1 (34, 4.183)-(78, 4.183) reference; L2 (34, -19)-(78, -19) reference; L3 (54, 4.183)-(54, -19); L4 (58, -19)-(58, 7); L5 (58, 7)-(54, 7); L6 (54, 7)-(54, 4.183); 1 further point
  constraints: 8 end point, 3 point on line, 2 parallel, 2 perpendicular
extrude "Extrusion182" join sketch "Sketch182" distance "d726" = 1; taper "d727" = 0 deg
sketch "Sketch183"
  geometry: L1 (-2, -7.408)-(113, -7.408); L2 (113, -7.408)-(113, -6); L3 (113, -6)-(-2, -6); L4 (-2, -6)-(-2, -7.408); L5 (113, -7.408)-(-2, -7.408); L6 (-2, -7.408)-(-2, -9); L7 (-2, -9)-(113, -9); L8 (113, -9)-(113, -7.408); 1 further point
  constraints: 16 end point, 4 parallel, 2 horizontal, 2 perpendicular
extrude "Extrusion183" join sketch "Sketch183" distance "d728" = 0.6; taper "d729" = 0 deg
chamfer "Chamfer110" distance "d730" = 0.6; stored, may be unused: second distance "d731" = 20.25, angle "d732" = 45 deg
chamfer "Chamfer111" distance "d733" = 1; stored, may be unused: second distance "d734" = 20.25, angle "d735" = 45 deg
chamfer "Chamfer112" distance "d736" = 2; stored, may be unused: second distance "d737" = 20.25, angle "d738" = 45 deg
sketch "Sketch184"
  geometry: L1 (-106.319, -22.522)-(-6.179, -22.522) reference; L2 (-82, -22.522)-(-28, -22.522); L3 (-28, -22.522)-(-28, -13); L4 (-28, -13)-(-82, -13); L5 (-82, -13)-(-82, -22.522); 1 further point
  constraints: 8 end point, 2 parallel, 1 horizontal, 1 perpendicular, 1 point on line
extrude "Extrusion184" join sketch "Sketch184" distance "d739" = 0.6; taper "d741" = 0 deg; dims "d740" = 2.8, "d742" = 0
chamfer "Chamfer113" distance "d743" = 2.5; stored, may be unused: second distance "d744" = 20.25, angle "d745" = 45 deg
chamfer "Chamfer114" distance "d746" = 0.5; stored, may be unused: second distance "d747" = 20.25, angle "d748" = 45 deg
chamfer "Chamfer115" distance "d749" = 0.5; stored, may be unused: second distance "d750" = 20.25, angle "d751" = 45 deg
chamfer "Chamfer116" distance "d752" = 0.5; stored, may be unused: second distance "d753" = 20.25, angle "d754" = 45 deg
chamfer "Chamfer117" distance "d755" = 19.9; stored, may be unused: second distance "d756" = 20.25, angle "d757" = 45 deg
body "Solid1"
